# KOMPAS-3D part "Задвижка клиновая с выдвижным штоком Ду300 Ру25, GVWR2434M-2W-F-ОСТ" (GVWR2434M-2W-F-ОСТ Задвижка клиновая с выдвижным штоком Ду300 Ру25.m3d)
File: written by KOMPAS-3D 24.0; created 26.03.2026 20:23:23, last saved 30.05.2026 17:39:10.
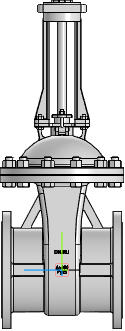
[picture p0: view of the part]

Document properties: Автор: R2D2; Полное имя файла: E:\Работа\Зайцев\GVWR2434M-2W-F-ОСТ Задвижка клиновая с выдвижным штоком DN.ru Ду50-300 Ру25\исходные материалы\DN300\DN300\GVWR2434M-2W-F-ОСТ Задвижка клиновая с выдвижным штоком Ду300 Ру25.m3d

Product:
- Part/product: Задвижка клиновая с выдвижным штоком Ду300 Ру25  | designation GVWR2434M-2W-F-ОСТ
    Масса: 265
    Раздел спецификации: Прочие изделия
    Примечание: D040-07592

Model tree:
1. Операция без истории:1

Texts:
  GVWR2434M-2W-F-ОСТ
